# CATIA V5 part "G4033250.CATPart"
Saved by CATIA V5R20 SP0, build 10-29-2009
Part number: G4033250
Revision: 3
Definition: design
Nomenclature: G4033250
Source: made
Description: NOT SPECIFIED
Bounding box of the stored display mesh (mm): x -25 to 25, y -22.5 to 22.5, z -22.5 to 22.5
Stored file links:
  C:\Users\Raffaele\Desktop\3D X SITO CF\BOLEX\27-BUSH REF 403\G4033250.CATPart
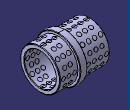
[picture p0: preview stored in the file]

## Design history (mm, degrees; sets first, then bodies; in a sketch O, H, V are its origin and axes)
Body1 "MANIFOLD_SOLID_BREP #13835" (main body)
  Solid1: solid without history
Body2 "MANIFOLD_SOLID_BREP #13986"
  Solid2: solid without history
Body3 "MANIFOLD_SOLID_BREP #14137"
  Solid3: solid without history
Body4 "MANIFOLD_SOLID_BREP #14288"
  Solid4: solid without history
Body5 "MANIFOLD_SOLID_BREP #14439"
  Solid5: solid without history
Body6 "MANIFOLD_SOLID_BREP #14588"
  Solid6: solid without history
Body7 "MANIFOLD_SOLID_BREP #14737"
  Solid7: solid without history
Body8 "MANIFOLD_SOLID_BREP #14886"
  Solid8: solid without history
Body9 "MANIFOLD_SOLID_BREP #15035"
  Solid9: solid without history
Body10 "MANIFOLD_SOLID_BREP #15184"
  Solid10: solid without history
Body11 "MANIFOLD_SOLID_BREP #15333"
  Solid11: solid without history
Body12 "MANIFOLD_SOLID_BREP #15482"
  Solid12: solid without history
Body13 "MANIFOLD_SOLID_BREP #15631"
  Solid13: solid without history
Body14 "MANIFOLD_SOLID_BREP #15780"
  Solid14: solid without history
Body15 "MANIFOLD_SOLID_BREP #15929"
  Solid15: solid without history
Body16 "MANIFOLD_SOLID_BREP #16078"
  Solid16: solid without history
Body17 "MANIFOLD_SOLID_BREP #16227"
  Solid17: solid without history
Body18 "MANIFOLD_SOLID_BREP #16376"
  Solid18: solid without history
Body19 "MANIFOLD_SOLID_BREP #16525"
  Solid19: solid without history
Body20 "MANIFOLD_SOLID_BREP #16674"
  Solid20: solid without history
Body21 "MANIFOLD_SOLID_BREP #16823"
  Solid21: solid without history
Body22 "MANIFOLD_SOLID_BREP #16972"
  Solid22: solid without history
Body23 "MANIFOLD_SOLID_BREP #17121"
  Solid23: solid without history
Body24 "MANIFOLD_SOLID_BREP #17270"
  Solid24: solid without history
Body25 "MANIFOLD_SOLID_BREP #17419"
  Solid25: solid without history
Body26 "MANIFOLD_SOLID_BREP #17568"
  Solid26: solid without history
Body27 "MANIFOLD_SOLID_BREP #17717"
  Solid27: solid without history
Body28 "MANIFOLD_SOLID_BREP #17866"
  Solid28: solid without history
Body29 "MANIFOLD_SOLID_BREP #18015"
  Solid29: solid without history
Body30 "MANIFOLD_SOLID_BREP #18164"
  Solid30: solid without history
Body31 "MANIFOLD_SOLID_BREP #18313"
  Solid31: solid without history
Body32 "MANIFOLD_SOLID_BREP #18464"
  Solid32: solid without history
Body33 "MANIFOLD_SOLID_BREP #18615"
  Solid33: solid without history
Body34 "MANIFOLD_SOLID_BREP #18764"
  Solid34: solid without history
Body35 "MANIFOLD_SOLID_BREP #18913"
  Solid35: solid without history
Body36 "MANIFOLD_SOLID_BREP #19062"
  Solid36: solid without history
Body37 "MANIFOLD_SOLID_BREP #19211"
  Solid37: solid without history
Body38 "MANIFOLD_SOLID_BREP #19360"
  Solid38: solid without history
Body39 "MANIFOLD_SOLID_BREP #19509"
  Solid39: solid without history
Body40 "MANIFOLD_SOLID_BREP #19658"
  Solid40: solid without history
Body41 "MANIFOLD_SOLID_BREP #19807"
  Solid41: solid without history
Body42 "MANIFOLD_SOLID_BREP #19956"
  Solid42: solid without history
Body43 "MANIFOLD_SOLID_BREP #20105"
  Solid43: solid without history
Body44 "MANIFOLD_SOLID_BREP #20254"
  Solid44: solid without history
Body45 "MANIFOLD_SOLID_BREP #20403"
  Solid45: solid without history
Body46 "MANIFOLD_SOLID_BREP #20552"
  Solid46: solid without history
Body47 "MANIFOLD_SOLID_BREP #20701"
  Solid47: solid without history
Body48 "MANIFOLD_SOLID_BREP #20850"
  Solid48: solid without history
Body49 "MANIFOLD_SOLID_BREP #20999"
  Solid49: solid without history
Body50 "MANIFOLD_SOLID_BREP #21148"
  Solid50: solid without history
Body51 "MANIFOLD_SOLID_BREP #21297"
  Solid51: solid without history
Body52 "MANIFOLD_SOLID_BREP #21446"
  Solid52: solid without history
Body53 "MANIFOLD_SOLID_BREP #21595"
  Solid53: solid without history
Body54 "MANIFOLD_SOLID_BREP #21746"
  Solid54: solid without history
Body55 "MANIFOLD_SOLID_BREP #21897"
  Solid55: solid without history
Body56 "MANIFOLD_SOLID_BREP #22048"
  Solid56: solid without history
Body57 "MANIFOLD_SOLID_BREP #22199"
  Solid57: solid without history
Body58 "MANIFOLD_SOLID_BREP #22348"
  Solid58: solid without history
Body59 "MANIFOLD_SOLID_BREP #22497"
  Solid59: solid without history
Body60 "MANIFOLD_SOLID_BREP #22646"
  Solid60: solid without history
Body61 "MANIFOLD_SOLID_BREP #22795"
  Solid61: solid without history
Body62 "MANIFOLD_SOLID_BREP #22944"
  Solid62: solid without history
Body63 "MANIFOLD_SOLID_BREP #23093"
  Solid63: solid without history
Body64 "MANIFOLD_SOLID_BREP #23242"
  Solid64: solid without history
Body65 "MANIFOLD_SOLID_BREP #23391"
  Solid65: solid without history
Body66 "MANIFOLD_SOLID_BREP #23540"
  Solid66: solid without history
Body67 "MANIFOLD_SOLID_BREP #23689"
  Solid67: solid without history
Body68 "MANIFOLD_SOLID_BREP #23838"
  Solid68: solid without history
Body69 "MANIFOLD_SOLID_BREP #23987"
  Solid69: solid without history
Body70 "MANIFOLD_SOLID_BREP #24136"
  Solid70: solid without history
Body71 "MANIFOLD_SOLID_BREP #24285"
  Solid71: solid without history
Body72 "MANIFOLD_SOLID_BREP #24434"
  Solid72: solid without history
Body73 "MANIFOLD_SOLID_BREP #24583"
  Solid73: solid without history
Body74 "MANIFOLD_SOLID_BREP #24732"
  Solid74: solid without history
Body75 "MANIFOLD_SOLID_BREP #24881"
  Solid75: solid without history
Body76 "MANIFOLD_SOLID_BREP #25030"
  Solid76: solid without history
Body77 "MANIFOLD_SOLID_BREP #25179"
  Solid77: solid without history
Body78 "MANIFOLD_SOLID_BREP #25328"
  Solid78: solid without history
Body79 "MANIFOLD_SOLID_BREP #25477"
  Solid79: solid without history
Body80 "MANIFOLD_SOLID_BREP #25626"
  Solid80: solid without history
Body81 "MANIFOLD_SOLID_BREP #25775"
  Solid81: solid without history
Body82 "MANIFOLD_SOLID_BREP #25924"
  Solid82: solid without history
Body83 "MANIFOLD_SOLID_BREP #26073"
  Solid83: solid without history
Body84 "MANIFOLD_SOLID_BREP #26222"
  Solid84: solid without history
Body85 "MANIFOLD_SOLID_BREP #26371"
  Solid85: solid without history
Body86 "MANIFOLD_SOLID_BREP #26520"
  Solid86: solid without history
Body87 "MANIFOLD_SOLID_BREP #26669"
  Solid87: solid without history
Body88 "MANIFOLD_SOLID_BREP #26818"
  Solid88: solid without history
Body89 "MANIFOLD_SOLID_BREP #26967"
  Solid89: solid without history
Body90 "MANIFOLD_SOLID_BREP #27116"
  Solid90: solid without history
Body91 "MANIFOLD_SOLID_BREP #27265"
  Solid91: solid without history
Body92 "MANIFOLD_SOLID_BREP #27414"
  Solid92: solid without history
Body93 "MANIFOLD_SOLID_BREP #27563"
  Solid93: solid without history
Body94 "MANIFOLD_SOLID_BREP #27714"
  Solid94: solid without history
Body95 "MANIFOLD_SOLID_BREP #27865"
  Solid95: solid without history
Body96 "MANIFOLD_SOLID_BREP #28016"
  Solid96: solid without history
Body97 "MANIFOLD_SOLID_BREP #28167"
  Solid97: solid without history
